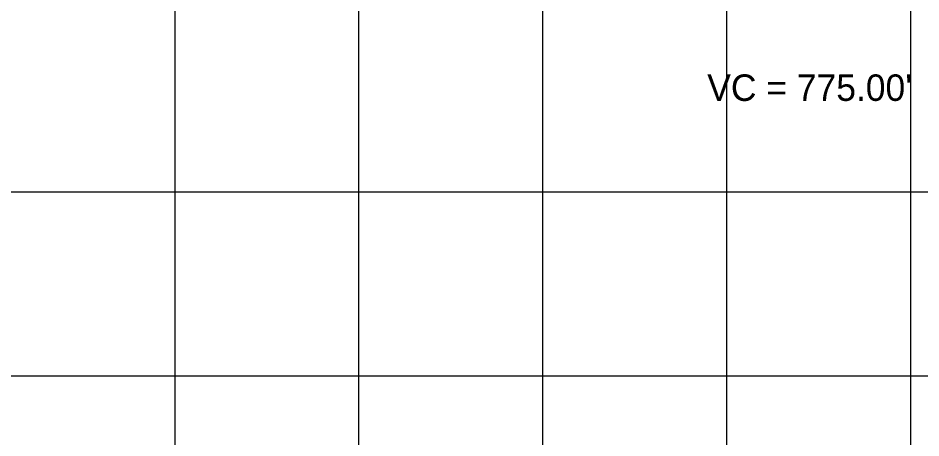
# Model space of a CAD drawing. Extents: x -7164 to 2214450, y -19642 to 253469.
# Drawn here: x 2057.4 to 2302.7, y -1766.9 to -1652.8 of the extents above; entities that cross this region are included whole.
import ezdxf

# ---------------------------------------------------------------- set-up
doc = ezdxf.new("R2010")
doc.units = 0
for name, color, linetype in [('DESIGN - PROFILE - Proposed', 7, 'Continuous'), ('DESIGN - PROFILE - Proposed Curve Text', 7, 'Continuous'), ('DESIGN - SHEET - Light Grid', 7, 'Continuous')]:
    doc.layers.add(name, color=color, linetype=linetype)

msp = doc.modelspace()

# ---------------------------------------------------------------- linework, layer by layer
at = {"layer": 'DESIGN - PROFILE - Proposed'}
msp.add_spline([(1885.96, -1477.23), (1901.46, -1478.04), (1916.96, -1478.98), (1932.46, -1480.07), (1947.96, -1481.29), (1963.46, -1482.65), (1978.96, -1484.15), (1994.46, -1485.79), (2009.96, -1487.57), (2025.46, -1489.49), (2040.96, -1491.54), (2056.46, -1493.73), (2071.96, -1496.07), (2087.46, -1498.54), (2102.96, -1501.15), (2118.46, -1503.9), (2133.96, -1506.79), (2149.46, -1509.81), (2164.96, -1512.98), (2180.46, -1516.28), (2195.96, -1519.72), (2211.46, -1523.3), (2226.96, -1527.02), (2242.46, -1530.88), (2257.96, -1534.88), (2273.46, -1539.01), (2288.96, -1543.29), (2304.46, -1547.7), (2319.96, -1552.25), (2335.46, -1556.94), (2350.96, -1561.77), (2366.46, -1566.74), (2381.96, -1571.85), (2397.46, -1577.09), (2412.96, -1582.48), (2428.46, -1588), (2443.96, -1593.66), (2459.46, -1599.46), (2474.96, -1605.4), (2490.46, -1611.48), (2505.96, -1617.69), (2521.46, -1624.05), (2536.96, -1630.54), (2552.46, -1637.18), (2567.96, -1643.95), (2583.46, -1650.86), (2598.96, -1657.9), (2614.46, -1665.09), (2629.96, -1672.42), (2645.46, -1679.88), (2660.96, -1687.48)], degree=3, dxfattribs=at)
msp.add_spline([(1885.96, -1477.23), (1901.46, -1478.04), (1916.96, -1478.98), (1932.46, -1480.07), (1947.96, -1481.29), (1963.46, -1482.65), (1978.96, -1484.15), (1994.46, -1485.79), (2009.96, -1487.57), (2025.46, -1489.49), (2040.96, -1491.54), (2056.46, -1493.73), (2071.96, -1496.07), (2087.46, -1498.54), (2102.96, -1501.15), (2118.46, -1503.9), (2133.96, -1506.79), (2149.46, -1509.81), (2164.96, -1512.98), (2180.46, -1516.28), (2195.96, -1519.72), (2211.46, -1523.3), (2226.96, -1527.02), (2242.46, -1530.88), (2257.96, -1534.88), (2273.46, -1539.01), (2288.96, -1543.29), (2304.46, -1547.7), (2319.96, -1552.25), (2335.46, -1556.94), (2350.96, -1561.77), (2366.46, -1566.74), (2381.96, -1571.85), (2397.46, -1577.09), (2412.96, -1582.48), (2428.46, -1588), (2443.96, -1593.66), (2459.46, -1599.46), (2474.96, -1605.4), (2490.46, -1611.48), (2505.96, -1617.69), (2521.46, -1624.05), (2536.96, -1630.54), (2552.46, -1637.18), (2567.96, -1643.95), (2583.46, -1650.86), (2598.96, -1657.9), (2614.46, -1665.09), (2629.96, -1672.42), (2645.46, -1679.88), (2660.96, -1687.48)], degree=3, dxfattribs=at)
at = {"layer": 'DESIGN - SHEET - Light Grid'}
for p, q in [((2100, -3000), (2100, -1000)), ((2100, -3000), (2100, -1000)), ((2150, -3000), (2150, -1000)), ((2150, -3000), (2150, -1000)), ((2200, -3000), (2200, -1000)), ((2200, -3000), (2200, -1000)), ((2250, -3000), (2250, -1000)), ((2250, -3000), (2250, -1000)), ((2300, -3000), (2300, -1000)), ((2300, -3000), (2300, -1000)), ((0, -1700), (12400, -1700)), ((0, -1700), (12400, -1700)), ((0, -1750), (12400, -1750)), ((0, -1750), (12400, -1750))]:
    msp.add_line(p, q, dxfattribs=at)

# ---------------------------------------------------------------- texts
at = {"layer": 'DESIGN - PROFILE - Proposed Curve Text'}
msp.add_text("VC = 775.00'", height=7.2, dxfattribs=at).set_placement((2244.64, -1675.27))
msp.add_text("VC = 775.00'", height=7.2, dxfattribs=at).set_placement((2244.64, -1675.27))

doc.saveas('drawing.dxf')
